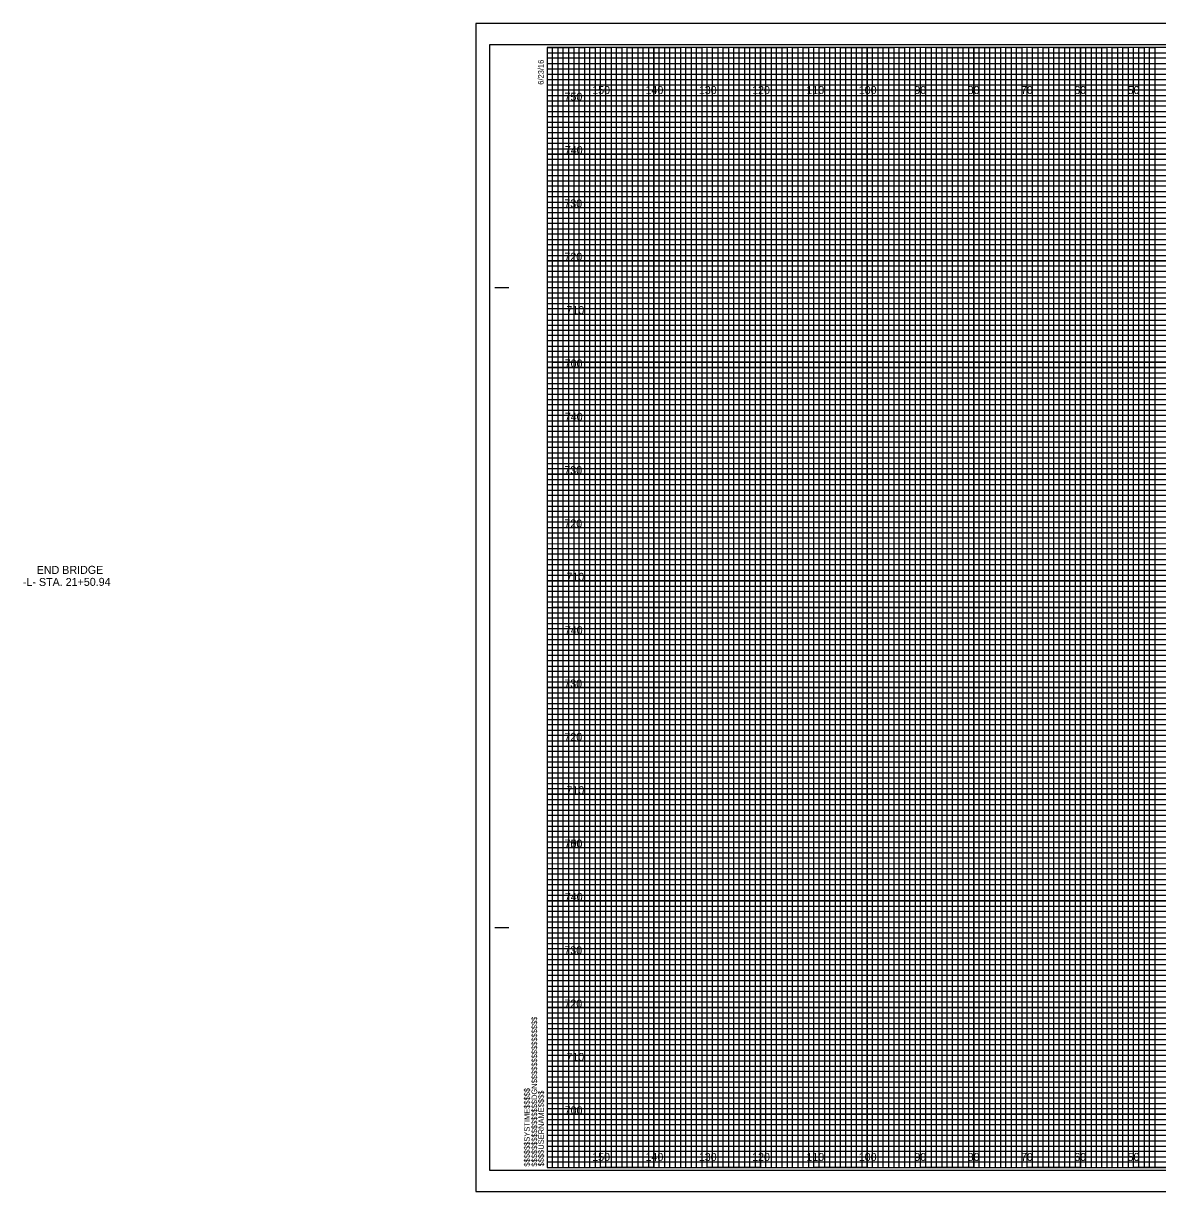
# Model space of a CAD drawing. Extents: x -98 to 717, y -10 to 1974.
# Drawn here: x -98.2 to 114.5, y 1095.5 to 1314.5 of the extents above; entities that cross this region are included whole.
import ezdxf

# ---------------------------------------------------------------- set-up
doc = ezdxf.new("R2010")
doc.units = 0
for name, color, linetype in [('Default', 7, 'Continuous'), ('Exist XS Center Line Elevation Label', 7, 'Continuous'), ('Prop CMT Conc Surface', 7, 'Continuous'), ('Prop CMT Concrete Structures', 7, 'Continuous'), ('Prop CMT Pvmt Course 1 CG', 7, 'Continuous'), ('Prop CMT Pvmt Course 2', 7, 'Continuous'), ('Prop CMT Pvmt Course 3', 7, 'Continuous'), ('Prop CMT Pvmt Surface', 7, 'Continuous'), ('Prop CMT Subgrade Earthwork', 7, 'Continuous'), ('Prop XS Ditch Standard Text', 7, 'Continuous'), ('Prop XS Dump Level', 7, 'Continuous'), ('Prop XS Earthwork Shape', 7, 'Continuous'), ('Prop XS Elevation Labels', 7, 'Continuous'), ('Typical Curb CELL', 7, 'Continuous')]:
    doc.layers.add(name, color=color, linetype=linetype)

msp = doc.modelspace()

# ---------------------------------------------------------------- linework, layer by layer
at = {"layer": 'Default'}
msp.add_lwpolyline([(-13.4, 1095.5), (323.3, 1095.5), (323.3, 1314.5), (-13.4, 1314.5)], close=True, dxfattribs=at)
at = {"layer": 'Exist XS Center Line Elevation Label'}
for p, q in [((0, 1309), (260, 1309)), ((260, 1307.98), (0, 1307.98)), ((0, 1307.98), (0, 1307)), ((0, 1307), (260, 1307)), ((260, 1305.89), (0, 1305.89)), ((0, 1305.89), (0, 1304)), ((0, 1304), (320, 1304))]:
    msp.add_line(p, q, dxfattribs=at)
for points in [[(0, 1303), (270, 1303), (320, 1303), (320, 1302), (0, 1302)], [(0, 1301), (320, 1301), (320, 1299), (0, 1299)], [(0, 1298), (320, 1298), (320, 1297), (0, 1296.98)], [(0, 1296), (320, 1296), (320, 1294), (0, 1294)], [(0, 1293), (320, 1293), (320, 1292), (0, 1292)], [(0, 1291), (320, 1291), (320, 1289), (0, 1289)], [(0, 1288), (320, 1288), (320, 1287), (0, 1287)], [(0, 1286), (320, 1286), (320, 1284), (0, 1284)], [(0, 1283), (320, 1283), (320, 1282), (0, 1282)], [(0, 1281), (320, 1281), (320, 1279), (0, 1279)], [(0, 1278), (320, 1278), (320, 1277), (0, 1277)], [(0, 1276), (320, 1276), (320, 1273.95), (320, 1273), (320, 1272), (0, 1272)], [(0, 1274), (320, 1274), (320, 1273), (0, 1273)], [(0, 1271), (320, 1271), (320, 1269), (0, 1269.03)], [(0, 1269.03), (320, 1269), (320, 1268), (0, 1268)], [(0, 1267), (320, 1267), (320, 1266), (0, 1266)], [(0, 1264), (320, 1264), (320, 1263), (0, 1263)], [(0, 1262), (320, 1262), (320, 1261), (0, 1261)], [(-0.07, 1258.89), (320, 1258.89), (320, 1257.88), (-0.07, 1257.88)], [(0, 1257), (320, 1257), (320, 1256), (0, 1256)], [(0, 1254), (320, 1254), (320, 1253), (0, 1253)], [(0, 1252), (320, 1252), (320, 1251), (0, 1251)], [(0, 1249), (320, 1249), (320, 1248), (0, 1248)], [(0, 1247), (320, 1247), (320, 1246), (0, 1246)], [(0, 1244), (320, 1244), (320, 1243), (0, 1243)], [(0, 1242), (320, 1242), (320, 1241), (0, 1241)], [(0, 1239), (320, 1239), (319.99, 1237.98), (0, 1238)], [(0, 1237), (320, 1237), (320, 1236), (0, 1236)], [(0, 1234), (320, 1234), (320, 1233), (0, 1233)], [(0, 1232), (320, 1232), (320, 1231), (0, 1231)], [(0, 1229), (320, 1229), (320, 1228), (0, 1228)], [(0, 1227), (320, 1227), (320, 1226), (0, 1226)], [(0, 1224), (320, 1224), (320, 1223), (0, 1223)], [(0, 1222), (320, 1222), (320, 1221), (0, 1221)], [(0, 1219), (320, 1219), (320, 1218), (0, 1218)], [(0, 1216.99), (320.07, 1216.91), (320, 1216), (0, 1216)], [(0, 1214), (320, 1214), (320, 1213), (0, 1213)], [(0, 1212), (320, 1212), (320, 1211), (0, 1211)], [(0, 1209), (320, 1209), (320, 1208), (0, 1208)], [(0, 1207), (320, 1207), (320, 1206), (0, 1206)], [(0, 1204), (320, 1204), (320, 1203), (0, 1203)], [(0, 1202), (320, 1202), (320, 1201), (0, 1201)], [(0, 1199), (320, 1199), (320, 1198), (0, 1198)], [(0, 1197), (320, 1197), (320, 1196), (0, 1196)], [(0, 1194), (320, 1194), (320, 1193), (0, 1193)], [(0, 1192), (320, 1192), (320, 1191), (0, 1191)], [(0, 1189), (320, 1189), (320, 1188), (0, 1188)], [(0, 1187), (320, 1187), (320, 1186), (0, 1186)], [(0, 1184), (320, 1184), (320, 1183), (0, 1183)], [(0, 1182), (320, 1182), (320, 1181), (0, 1181)], [(0, 1179), (320, 1179), (319.99, 1177.98), (0, 1178)], [(0, 1177), (320, 1177), (320, 1176), (0, 1176)], [(0, 1174), (320, 1174), (320, 1173), (0, 1173)], [(0, 1172), (320, 1172), (320, 1171), (0, 1171)], [(0, 1169), (320, 1169), (320, 1168), (0, 1168)], [(0, 1167), (320, 1167), (320, 1166), (0, 1166)], [(0, 1164), (320, 1164), (320, 1163), (0, 1163)], [(0, 1162), (320, 1162), (320, 1161), (0, 1161)], [(0, 1159), (320, 1159), (320, 1158), (0, 1158)], [(0, 1156.99), (320.07, 1156.91), (320, 1156), (0, 1156)], [(0, 1154), (320, 1154), (320, 1153), (0, 1153)], [(0, 1152), (320, 1152), (320, 1151), (0, 1151)], [(0, 1149), (320, 1149), (320, 1148), (0, 1148)], [(0, 1147), (320, 1147), (320, 1146), (0, 1146)], [(0, 1144), (320, 1144), (320, 1143), (0, 1143)], [(0, 1142), (320, 1142), (320, 1141), (0, 1141)], [(0, 1139), (320, 1139), (320, 1138), (0, 1138)], [(0, 1137), (320, 1137), (320, 1136), (0, 1136)], [(0, 1134), (320, 1134), (320, 1133), (0, 1133)], [(0, 1132), (320, 1132), (320, 1131), (0, 1131)], [(0, 1129), (320, 1129), (320, 1128), (0, 1128)], [(0, 1127), (320, 1127), (320, 1126), (0, 1126)], [(0, 1124), (320, 1124), (320, 1123), (0, 1123)], [(0, 1122), (320, 1122), (320, 1121), (0, 1121)], [(0, 1119), (320, 1119), (320, 1118), (0, 1118)], [(0, 1117), (320, 1117), (320, 1116), (0, 1116)], [(0, 1114), (320, 1114), (320, 1113), (0, 1113)], [(0, 1112), (320, 1112), (320, 1111), (0, 1111)], [(0, 1109), (320, 1109), (320, 1108), (0, 1108)], [(0, 1107), (320, 1107), (320, 1106), (0, 1106)], [(0, 1104), (320, 1104), (320, 1103), (0, 1103)], [(0, 1102), (320, 1102), (320, 1101), (0, 1101)]]:
    msp.add_lwpolyline(points, dxfattribs=at)
at = {"layer": 'Prop CMT Conc Surface'}
for p, q in [((-9.8, 1265), (-7.3, 1265)), ((-9.7, 1265), (-7.2, 1265)), ((-9.8, 1145), (-7.3, 1145)), ((-9.7, 1145), (-7.2, 1145)), ((0, 1100), (0, 1100)), ((0, 1100), (0, 1100)), ((0, 1100), (0, 1100)), ((0, 1100), (0, 1100)), ((0, 1100), (0, 1100)), ((0, 1100), (0, 1100)), ((0, 1100), (0, 1100))]:
    msp.add_line(p, q, dxfattribs=at)
msp.add_lwpolyline([(320, 1310), (0, 1310), (0, 1100), (320, 1100)], close=True, dxfattribs=at)
at = {"layer": 'Prop CMT Concrete Structures'}
for p, q in [((10, 1100), (10, 1310)), ((20, 1100), (20, 1310)), ((30, 1100), (30, 1310)), ((40, 1100), (40, 1310)), ((50, 1100), (50, 1310)), ((60, 1100), (60, 1310)), ((70, 1100), (70, 1310)), ((80, 1100), (80, 1310)), ((90, 1100), (90, 1310)), ((100, 1100), (100, 1310)), ((110, 1100), (110, 1310)), ((0, 1300), (320, 1300)), ((0, 1290), (320, 1290)), ((0, 1280), (320, 1280)), ((0, 1270), (320, 1270)), ((0, 1260), (320, 1260)), ((0, 1250), (320, 1250)), ((0, 1240), (320, 1240)), ((0, 1230), (320, 1230)), ((0, 1220), (320, 1220)), ((0, 1210), (320, 1210)), ((0, 1200), (320, 1200)), ((0, 1190), (320, 1190)), ((0, 1180), (320, 1180)), ((0, 1170), (320, 1170)), ((0, 1160), (320, 1160)), ((0, 1150), (320, 1150)), ((0, 1140), (320, 1140)), ((0, 1130), (320, 1130)), ((0, 1120), (320, 1120)), ((0, 1110), (320, 1110))]:
    msp.add_line(p, q, dxfattribs=at)
at = {"layer": 'Prop CMT Pvmt Course 2'}
msp.add_lwpolyline([(-13.4, 1095.5), (323.3, 1095.5), (323.3, 1314.5), (-13.4, 1314.5)], close=True, dxfattribs=at)
at = {"layer": 'Prop CMT Pvmt Course 3'}
msp.add_lwpolyline([(-10.8, 1099.5), (322.4, 1099.5), (322.4, 1310.5), (-10.8, 1310.5)], close=True, dxfattribs=at)
at = {"layer": 'Prop CMT Pvmt Surface'}
for p, q in [((323.3, 1314.5), (-13.4, 1314.5)), ((-13.4, 1314.5), (-13.4, 1095.5)), ((-13.4, 1095.5), (323.3, 1095.5))]:
    msp.add_line(p, q, dxfattribs=at)
at = {"layer": 'Prop CMT Subgrade Earthwork'}
for points in [[(0, 1100), (1, 1100), (1, 1310), (2, 1310), (2, 1100)], [(2, 1100), (3, 1100), (3, 1310), (4, 1310), (4, 1100)], [(5, 1100), (6, 1100), (6, 1310), (7, 1310), (7, 1100)], [(7, 1100), (8, 1100), (8, 1310), (9, 1310), (9, 1100)], [(10, 1100), (11, 1100), (11, 1310), (12, 1310), (12, 1100)], [(12, 1100), (13, 1100), (13, 1310), (14, 1310), (14, 1100)], [(15, 1100), (16, 1100), (16, 1310), (17, 1310), (17, 1100)], [(17, 1100), (18, 1100), (18, 1310), (19, 1310), (19, 1100)], [(20, 1100), (21, 1100), (21, 1310), (22, 1310), (22, 1100)], [(22, 1100), (23, 1100), (23, 1310), (24, 1310), (24, 1100)], [(25, 1100), (26, 1100), (26, 1310), (27, 1310), (27, 1100)], [(27, 1100), (28, 1100), (28, 1310), (29, 1310), (29, 1100)], [(30, 1100), (31, 1100), (31, 1310), (32, 1310), (32, 1100)], [(32, 1100), (33, 1100), (33, 1310), (34, 1310), (34, 1100)], [(35, 1100), (36, 1100), (36, 1310), (37, 1310), (37, 1100)], [(37, 1100), (38, 1100), (38, 1310), (39, 1310), (39, 1100)], [(40, 1100), (41, 1100), (41, 1310), (42, 1310), (42, 1100)], [(42, 1100), (43, 1100), (43, 1310), (44, 1310), (44, 1100)], [(45, 1100), (46, 1100), (46, 1310), (47, 1310), (47, 1100)], [(47, 1100), (48, 1100), (48, 1310), (49, 1310), (49, 1100)], [(50, 1100), (51, 1100), (51, 1310), (52, 1310), (52, 1100)], [(52, 1100), (53, 1100), (53, 1310), (54, 1310), (54, 1100)], [(55, 1100), (56, 1100), (56, 1310), (57, 1310), (57, 1100)], [(57, 1100), (58, 1100), (58, 1310), (59, 1310), (59, 1100)], [(60, 1100), (61, 1100), (61, 1310), (62, 1310), (62, 1100)], [(62, 1100), (63, 1100), (63, 1310), (64, 1310), (64, 1100)], [(65, 1100), (66, 1100), (66, 1310), (67, 1310), (67, 1100)], [(67, 1100), (68, 1100), (68, 1310), (69, 1310), (69, 1100)], [(70, 1100), (71, 1100), (71, 1310), (72, 1310), (72, 1100)], [(72, 1100), (73, 1100), (73, 1310), (74, 1310), (74, 1100)], [(75, 1100), (76, 1100), (76, 1310), (77, 1310), (77, 1100)], [(77, 1100), (78, 1100), (78, 1310), (79, 1310), (79, 1100)], [(80, 1100), (81, 1100), (81, 1310), (82, 1310), (82, 1100)], [(82, 1100), (83, 1100), (83, 1310), (84, 1310), (84, 1100)], [(85, 1100), (86, 1100), (86, 1310), (87, 1310), (87, 1100)], [(87, 1100), (88, 1100), (88, 1310), (89, 1310), (89, 1100)], [(90, 1100), (91, 1100), (91, 1310), (92, 1310), (92, 1100)], [(92, 1100), (93, 1100), (93, 1310), (94, 1310), (94, 1100)], [(95, 1100), (96, 1100), (96, 1310), (97, 1310), (97, 1100)], [(97, 1100), (98, 1100), (98, 1310), (99, 1310), (99, 1100)], [(100, 1100), (101, 1100), (101, 1310), (102, 1310), (102, 1100)], [(102, 1100), (103, 1100), (103, 1310), (104, 1310), (104, 1100)], [(105, 1100), (106, 1100), (106, 1310), (107, 1310), (107, 1100)], [(107, 1100), (108, 1100), (108, 1310), (109, 1310), (109, 1100)], [(110, 1100), (111, 1100), (111, 1310), (112, 1310), (112, 1100)], [(112, 1100), (113, 1100), (113, 1310), (114, 1310), (114, 1100)]]:
    msp.add_lwpolyline(points, dxfattribs=at)
at = {"layer": 'Prop XS Ditch Standard Text'}
msp.add_lwpolyline([(1, 1251), (314, 1251), (314, 1205), (1, 1205)], close=True, dxfattribs=at)
at = {"layer": 'Prop XS Elevation Labels'}
for p, q in [((10, 1310), (0, 1310)), ((10, 1100), (10, 1310)), ((30, 1310), (20, 1310)), ((20, 1310), (20, 1100)), ((30, 1100), (30, 1310)), ((50, 1310), (40, 1310)), ((40, 1310), (40, 1100)), ((50, 1100), (50, 1310)), ((70, 1310), (60, 1310)), ((60, 1310), (60, 1100)), ((70, 1100), (70, 1310)), ((90, 1310), (80, 1310)), ((80, 1310), (80, 1100)), ((90, 1100), (90, 1310)), ((110, 1310), (100, 1310)), ((100, 1310), (100, 1100)), ((110, 1100), (110, 1310)), ((20, 1100), (10, 1100)), ((40, 1100), (30, 1100)), ((60, 1100), (50, 1100)), ((80, 1100), (70, 1100)), ((100, 1100), (90, 1100)), ((120, 1100), (110, 1100))]:
    msp.add_line(p, q, dxfattribs=at)
for points in [[(0, 1300), (320, 1300), (320, 1290), (0, 1290)], [(0, 1280), (320, 1280), (320, 1270), (0, 1270)], [(0, 1260), (320, 1260), (320, 1250), (0, 1250)], [(0, 1240), (320, 1240), (320, 1230), (0, 1230)], [(0, 1220), (320, 1220), (320, 1210), (0, 1210)], [(0, 1200), (320, 1200), (320, 1190), (0, 1190)], [(0, 1180), (320, 1180), (320, 1170), (0, 1170)], [(0, 1160), (320, 1160), (320, 1150), (0, 1150)], [(0, 1140), (320, 1140), (320, 1130), (0, 1130)], [(0, 1120), (320, 1120), (320, 1110), (0, 1110)]]:
    msp.add_lwpolyline(points, dxfattribs=at)
at = {"layer": 'Typical Curb CELL'}
for points in [[(0, 1310), (5, 1310), (5, 1100), (15, 1100), (15, 1310), (25, 1310), (25, 1100), (35, 1100), (35, 1310), (45, 1310), (45, 1100), (55, 1100), (55, 1310), (65, 1310), (65, 1100), (75, 1100), (75, 1310), (85, 1310), (85, 1100), (95, 1100), (95, 1310), (105, 1310), (105, 1100), (115, 1100)], [(0, 1305), (275, 1305)], [(0, 1285), (320, 1285), (320, 1295), (0, 1295)], [(0, 1265), (320, 1265), (320, 1275), (0, 1275)], [(0, 1245), (320, 1245), (320, 1255), (0, 1255)], [(0, 1225), (320, 1225), (320, 1235), (0, 1235)], [(0, 1205), (320, 1205), (320, 1215), (0, 1215)], [(0, 1185), (320, 1185), (320, 1195), (0, 1195)], [(0, 1165), (320, 1165), (320, 1175), (0, 1175)], [(0, 1145), (320, 1145), (320, 1155), (0, 1155)], [(0, 1125), (320, 1125), (320, 1135), (0, 1135)], [(0, 1105), (320, 1105), (320, 1115), (0, 1115)]]:
    msp.add_lwpolyline(points, dxfattribs=at)

# ---------------------------------------------------------------- texts
at = {"layer": 'Prop CMT Conc Surface'}
for s, p in [('6/23/16', (-0.65, 1303)), ('$$$$$$$$$$$$$$$$DGN$$$$$$$$$$$$$$$$', (-1.88, 1100.18)), ('$$$$$$SYSTIME$$$$$', (-3.26, 1100.18)), ('$$$$USERNAME$$$$', (-0.62, 1100.23))]:
    msp.add_text(s, height=1.05, rotation=90, dxfattribs=at).set_placement(p)
at = {"layer": 'Prop CMT Pvmt Course 1 CG'}
for s, p in [('750', (3.25, 1300)), ('740', (3.3, 1290)), ('730', (3.22, 1280)), ('720', (3.23, 1270)), ('710', (3.61, 1260)), ('700', (3.28, 1250)), ('740', (3.3, 1240)), ('730', (3.22, 1230)), ('720', (3.23, 1220)), ('710', (3.61, 1210)), ('740', (3.3, 1200)), ('730', (3.22, 1190)), ('720', (3.23, 1180)), ('710', (3.61, 1170)), ('750', (3.25, 1160)), ('700', (3.28, 1160)), ('740', (3.3, 1150)), ('730', (3.22, 1140)), ('720', (3.23, 1130)), ('710', (3.61, 1120)), ('700', (3.28, 1110))]:
    msp.add_text(s, height=1.5, dxfattribs=at).set_placement(p)
at = {"layer": 'Prop XS Dump Level'}
for s, p in [('END BRIDGE', (-95.74, 1211.28)), ('-L- STA. 21+50.94', (-98.33, 1209.02))]:
    msp.add_text(s, height=1.5, rotation=0.1418, dxfattribs=at).set_placement(p)
at = {"layer": 'Prop XS Earthwork Shape'}
for s, p in [('150', (8.44, 1301.25)), ('140', (18.44, 1301.25)), ('130', (28.44, 1301.25)), ('120', (38.44, 1301.25)), ('110', (48.62, 1301.25)), ('100', (58.44, 1301.25)), ('90', (68.86, 1301.25)), ('80', (78.86, 1301.25)), ('70', (88.86, 1301.25)), ('60', (98.86, 1301.25)), ('50', (108.86, 1301.25)), ('150', (8.44, 1101.25)), ('140', (18.44, 1101.25)), ('130', (28.44, 1101.25)), ('120', (38.44, 1101.25)), ('110', (48.62, 1101.25)), ('100', (58.44, 1101.25)), ('90', (68.86, 1101.25)), ('80', (78.86, 1101.25)), ('70', (88.86, 1101.25)), ('60', (98.86, 1101.25)), ('50', (108.86, 1101.25))]:
    msp.add_text(s, height=1.5, dxfattribs=at).set_placement(p)

doc.saveas('drawing.dxf')
